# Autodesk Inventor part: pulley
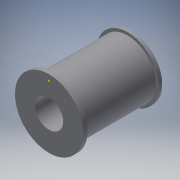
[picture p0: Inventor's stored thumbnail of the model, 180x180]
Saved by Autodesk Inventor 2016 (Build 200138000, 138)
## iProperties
Created: 2016-02
Part Number: pulley
Material: Generic
Document SubType Name: Modeling
Designer: Juha-Pekka
Density: 1 g/cm^3
Appearance: Default
Author: Juha-Pekka
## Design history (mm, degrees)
sketch "Sketch1"
  geometry: L1 (0, 0)-(0, 1.212); L2 (0, 1.212)-(0.949, 1.212); L3 (0.949, 1.212)-(0.949, 0); L4 (0.949, 0)-(16.789, 0); L5 (16.789, 0)-(16.789, 0.606); L6 (16.789, 0.606)-(17.489, 0.606); L7 (17.489, 0.606)-(17.489, 0); L8 (8.432, -6.074)-(0, -6.074); L9 (0, -6.074)-(17.489, -6.074); L10 (17.489, 0)-(17.489, -6.074); L11 (0, 0)-(0, -6.074)
  constraints: 22 end point, 5 perpendicular, 2 horizontal, 2 point on line, 2 vertical, 1 parallel
revolve "Revolution1" sketch "Sketch1" stored, may be unused: angle "d1" = 5 deg
sketch "Sketch2"
  geometry: C1 r 3 at (0, 0); 1 further point
  constraints: 1 centre point
  dimensions: "d2" = 6 diameter of C1
hole "Hole1" sketch "Sketch2" at (0, 0) diameter "d3" = 6; stored, may be unused: countersink angle "d7" = 90 deg, drill point angle "d9" = 118 deg; dims "d4" = 6, "d5" = 4, "d6" = 2, "d8" = 8
sketch "Sketch3"
  geometry: 1 further point
body "Solid1"
